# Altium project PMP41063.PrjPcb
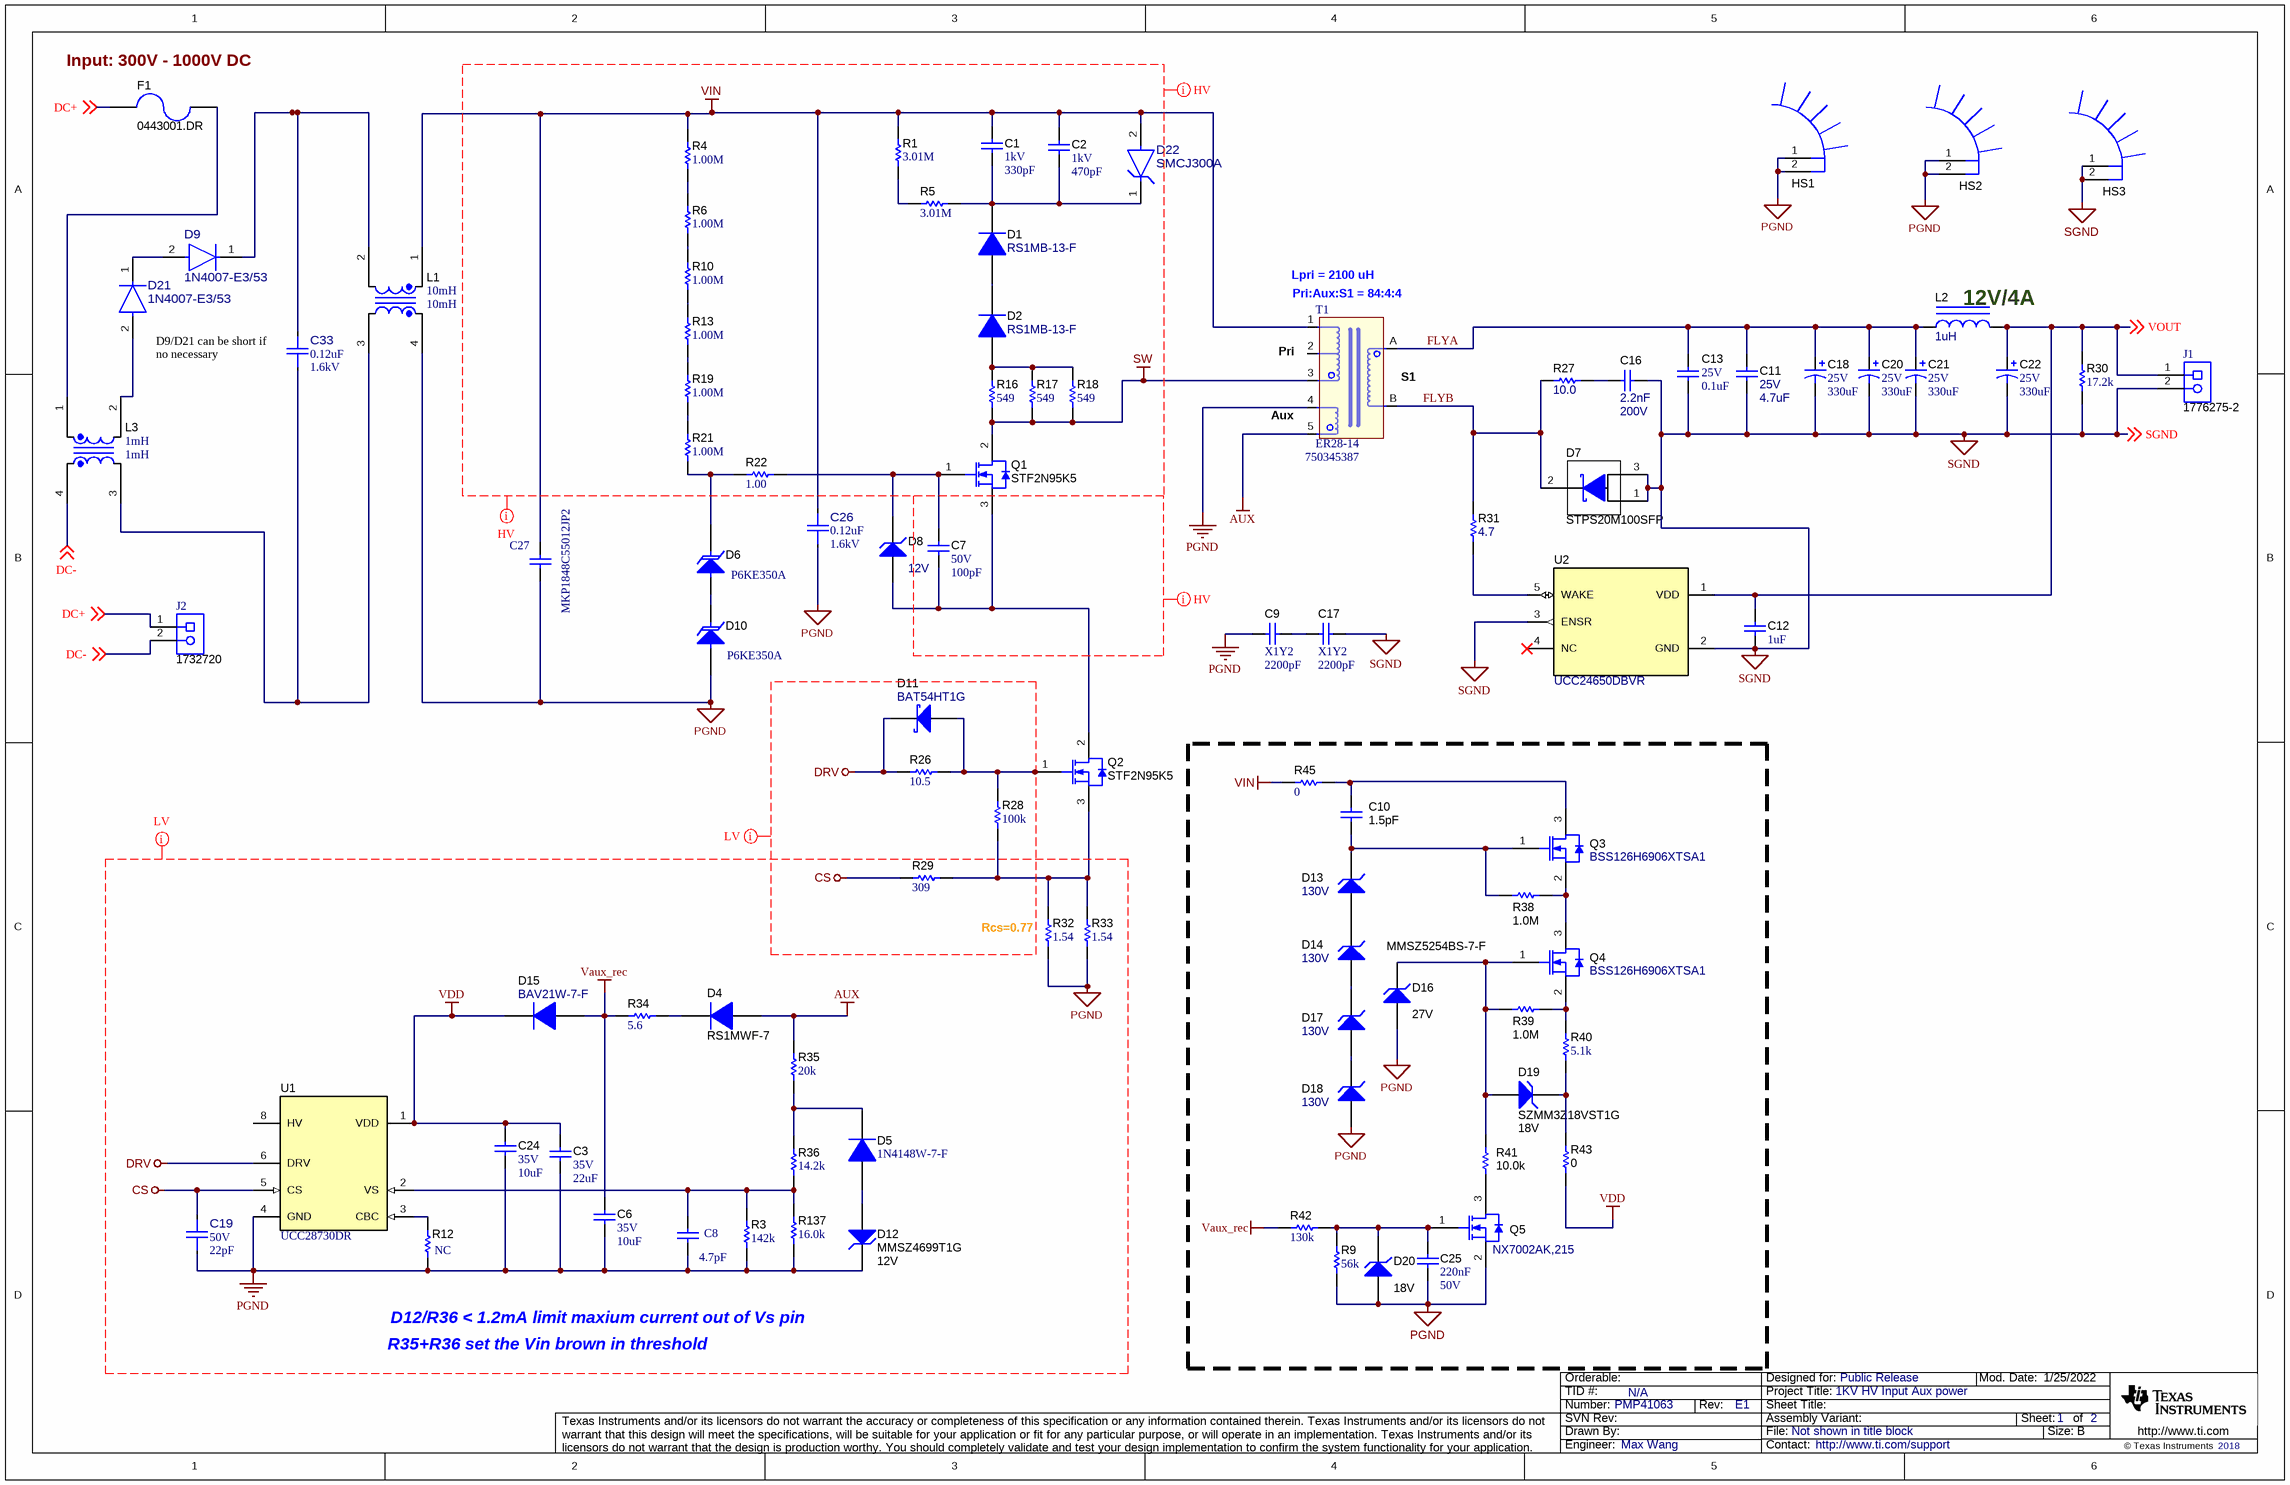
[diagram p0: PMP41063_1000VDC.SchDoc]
CopyrightYear: 2018; PCB_Layout: Max Wang; PCB_Rev: E1; PRJ_Customer: Public Release; PRJ_Engineer: Max Wang; PRJ_Number: PMP41063; PRJ_Title: 1KV HV Input Aux power; SCH_Rev: E1; TechSupport: http://www.ti.com/support; TID: N/A
2 sheets, 105 parts. Net scope: global (net labels, ports and power ports of the same name join across sheets).
Board file: PMP41063.PcbDoc
Sheets:
  PMP41063_1000VDC.SchDoc
  PMP41063_2_Hardware.SchDoc

## Sheet PMP41063_1000VDC.SchDoc
size 431 x 279 mm; Date: Not shown in title block; ApprovedBy: Not shown in title block; CheckedBy: Not shown in title block; Author: Not shown in title block; CompanyName: Not shown in title block; Engineer: Not shown in title block; Organization: Not shown in title block; Address1: Not shown in title block; Address2: Not shown in title block; Address3: Not shown in title block; Address4: Not shown in title block; DocumentNumber: 2; Revision: Use project parameter SCH_Rev; SheetNumber: 1; SheetTotal: 2; PageSetup: Record=PageOptions¦CenterHorizontal=True¦CenterVertical=True¦PrintScale=1.00¦XCorrection=1.00¦YCorrection=1.00¦PrintKind=0¦BorderSize=5000000¦LeftOffset=0¦BottomOffset=0¦Orientation=2¦PaperLength=1000¦PaperWidth=1000¦Scale=100¦PaperSource=15¦PrintQuality=600¦MediaType=1¦DitherType=10¦PaperKind=Letter¦PrintScaleMode=1

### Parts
C1  VDC_V: 1kV  ValueDisplayed: 330pF  [1206]  (hidden comment: GRM31A7U3A331JW31D)
C2  VDC_V: 1kV  ValueDisplayed: 470pF  [1206]  (hidden comment: VJ1206A471JXGAT5Z)
C3  VDC_V: 35V  ValueDisplayed: 22uF  [1206_180]  (hidden comment: C3216X5R1V226M160AC)
C6  VDC_V: 35V  ValueDisplayed: 10uF  [0805_HV]  (hidden comment: GRM21BR6YA106KE43L)
C7  VDC_V: 50V  ValueDisplayed: 100pF  [0805_HV]  (hidden comment: 885012007057)
C8  value 4.7pF  [WCAP-CSGP_0603_L1.6W0.8H0.8_Reflow]  (hidden comment: 885012006030)
C9  AC_Safety: X1Y2  ValueDisplayed: 2200pF  [VY2_900x500_5]  (hidden comment: VY2222M35Y5UG6TV5)
C10  ValueDisplayed: 1.5pF  [1206]  (hidden comment: 1206Y1K01P50DAR)
C11  VDC_V: 25V  ValueDisplayed: 4.7uF  [1206_180]  (hidden comment: GRM31CR71E475KA88L)
C12  ValueDisplayed: 1uF  [0603]  (hidden comment: CMP-0007040-4)
C13  VDC_V: 25V  ValueDisplayed: 0.1uF  [0805_HV]  (hidden comment: GRM21BR71E104KA01L)
C16  Cap_F: 2.2nF  VDC_V: 200V  [0805_HV]  (hidden comment: C0805C222K2RAC)
C17  AC_Safety: X1Y2  ValueDisplayed: 2200pF  [VY2_900x500_5]  (hidden comment: VY2222M35Y5UG6TV5)
C18  VDC_V: 25V  ValueDisplayed: 330uF  [SM_RADIAL_10BMM]  (hidden comment: EEHZC1E331P)
C19  VDC_V: 50V  ValueDisplayed: 22pF  [FP-GCG1885G1H220JA01D_0603-IPC_C]  (hidden comment: GCG1885G1H220JA01D)
C20  VDC_V: 25V  ValueDisplayed: 330uF  [SM_RADIAL_10BMM]  (hidden comment: EEHZC1E331P)
C21  VDC_V: 25V  ValueDisplayed: 330uF  [SM_RADIAL_10BMM]  (hidden comment: EEHZC1E331P)
C22  VDC_V: 25V  ValueDisplayed: 330uF  [SM_RADIAL_10BMM]  (hidden comment: EEHZC1E331P)
C24  VDC_V: 35V  ValueDisplayed: 10uF  [0805_HV]  (hidden comment: GRM21BR6YA106KE43L)
C25  Cap_F: 220nF  VDC_V: 50V  [0603]  (hidden comment: GCJ188R71H224KA01D)
C26  ValueDisplayed: 0.12uF  VDC_V: 1.6kV  [FP-R75TN312050H3J_RADIAL-MFG]  (hidden comment: R75TN312050H3J)
C27  MKP1848C55012JP2  [WCAP-FTBE_L42W31H43]
C33  ValueDisplayed: 0.12uF  VDC_V: 1.6kV  [FP-R75TN312050H3J_RADIAL-MFG]  (hidden comment: R75TN312050H3J)
D1  RS1MB-13-F  [SMB]
D2  RS1MB-13-F  [SMB]
D4  RS1MWF-7  [SOD-123F]
D5  1N4148W-7-F  [SOD-123]
D6  PartNumber: P6KE350A  [DO-15]  (hidden comment: CMP-0006021-3)
D7  STPS20M100SFP  [TO-220FP]
D8  value 12V  [SOD-123]  (hidden comment: MMSZ4699-HE3-08)
D9  1N4007-E3/53  [FP-1N4007-E3/53_DO-41-MFG]
D10  PartNumber: P6KE350A  [DO-15]  (hidden comment: CMP-0006021-3)
D11  BAT54HT1G  [SOD-323]
D12  MMSZ4699T1G  value 12V  [SOD-123]
D13  value 130V  [SOD-323F]  (hidden comment: UDZLVFHTE-17130)
D14  value 130V  [SOD-323F]  (hidden comment: UDZLVFHTE-17130)
D15  BAV21W-7-F  [SOD-123]
D16  MMSZ5254BS-7-F  value 27V  [SOD-323]
D17  value 130V  [SOD-323F]  (hidden comment: UDZLVFHTE-17130)
D18  value 130V  [SOD-323F]  (hidden comment: UDZLVFHTE-17130)
D19  SZMM3Z18VST1G  value 18V  [SOD-323]
D20  value 18V  [SOD-323]  (hidden comment: SZMM3Z18VST1G)
D21  1N4007-E3/53  [FP-1N4007-E3/53_DO-41-MFG]
D22  SMCJ300A  [FP-SMCJ300A_DO214AB-MFG]
F1  0443001.DR  [FUSE_0443]
HS1  CMP-0004071-1  [Aavid_513102B02500G]  (value not drawn)
HS2  CMP-0004071-1  [Aavid_513102B02500G]  (value not drawn)
HS3  CMP-0004071-1  [Aavid_513102B02500G]  (value not drawn)
J1  1776275-2  [TE_1776275-2]
J2  1732720  [Phoenix_1732720]
L1  value 10mH  [WE-CMB_XS]  (hidden comment: 744821110)
L2  ValueDisplayed: 1uH  [WE-PD_7345]  (hidden comment: 744777001)
L3  value 1mH  [WE-CMB_XS]  (hidden comment: 744821201)
Q1  STF2N95K5  [TO-220_FullPAK_Offset]
Q2  STF2N95K5  [TO-220_FullPAK_Offset]
Q3  BSS126H6906XTSA1  [SOT-23]
Q4  BSS126H6906XTSA1  [SOT-23]
Q5  NX7002AK,215  [SOT-23]
R1  ValueDisplayed: 3.01M  [1206]  (hidden comment: CRCW12063M01FKEA)
R3  ValueDisplayed: 142k  [0603]  (hidden comment: RT0603BRD07142KL)
R4  ValueDisplayed: 1.00M  [1206]  (hidden comment: ERJ-8ENF1004V)
R5  ValueDisplayed: 3.01M  [1206]  (hidden comment: CRCW12063M01FKEA)
R6  ValueDisplayed: 1.00M  [1206]  (hidden comment: ERJ-8ENF1004V)
R9  ValueDisplayed: 56k  [0603]  (hidden comment: CRCW060356K0JNEA)
R10  ValueDisplayed: 1.00M  [1206]  (hidden comment: ERJ-8ENF1004V)
R12  Parameter 1: NC  [0603]  (hidden comment: RC0603FR-0751K1L)
R13  ValueDisplayed: 1.00M  [1206]  (hidden comment: ERJ-8ENF1004V)
R16  ValueDisplayed: 549  [1210]  (hidden comment: RC1210FR-07549RL)
R17  ValueDisplayed: 549  [1210]  (hidden comment: RC1210FR-07549RL)
R18  ValueDisplayed: 549  [1210]  (hidden comment: RC1210FR-07549RL)
R19  ValueDisplayed: 1.00M  [1206]  (hidden comment: ERJ-8ENF1004V)
R21  ValueDisplayed: 1.00M  [1206]  (hidden comment: ERJ-8ENF1004V)
R22  ValueDisplayed: 1.00  [1206]  (hidden comment: RC1206FR-071RL)
R26  ValueDisplayed: 10.5  [0805_HV]  (hidden comment: CRCW080510R5FKEA)
R27  ValueDisplayed: 10.0  [0805_HV]  (hidden comment: RC0805FR-0710RL)
R28  ValueDisplayed: 100k  [0603]  (hidden comment: RC0603FR-07100KL)
R29  ValueDisplayed: 309  [0603]  (hidden comment: CRCW0603309RFKEA)
R30  ValueDisplayed: 17.2k  [0805_HV]  (hidden comment: RT0805BRD0717K2L)
R31  ValueDisplayed: 4.7  [0603]  (hidden comment: CRCW06034R70JNEA)
R32  ValueDisplayed: 1.54  [0805_HV]  (hidden comment: CRCW08051R54FKEA)
R33  ValueDisplayed: 1.54  [0805_HV]  (hidden comment: CRCW08051R54FKEA)
R34  ValueDisplayed: 5.6  [0805_HV]  (hidden comment: RC0805JR-075R6L)
R35  ValueDisplayed: 20k  [0603]  (hidden comment: RC0603JR-0720KL)
R36  ValueDisplayed: 14.2k  [0603]  (hidden comment: RT0603BRD0714K2L)
R38  ValueDisplayed: 1.0M  [0603]  (hidden comment: CRCW06031M00JNEA)
R39  ValueDisplayed: 1.0M  [0603]  (hidden comment: CRCW06031M00JNEA)
R40  ValueDisplayed: 5.1k  [0603]  (hidden comment: RC0603JR-075K1L)
R41  ValueDisplayed: 10.0k  [0603]  (hidden comment: CRCW060310K0FKEA)
R42  ValueDisplayed: 130k  [0603]  (hidden comment: RT0603BRD07130KL)
R43  ValueDisplayed: 0  [1206]  (hidden comment: CRCW12060000Z0EA)
R45  ValueDisplayed: 0  [0603]  (hidden comment: CRCW06030000Z0EA)
R137  ValueDisplayed: 16.0k  [0603]  (hidden comment: RC0603FR-0716KL)
T1  ER28-14  PartNumber: 750345387  [ER28-14]
U1  UCC28730DR  [D0007A_N]
U2  UCC24650DBVR  [DBV0005A_N]

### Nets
AUX: D4.2(A) R35.2 T1.5
CS: C19.2 R29.1 U1.5(CS)
DRV: D11.1(K) R26.1 U1.6(DRV)
PGND: C3.2 C6.2 C8.1 C9.1 C19.1 C24.2 C25.2 C26.1 C27.1 D10.2(A) D12.1(K) D16.2(A) D18.2(A) D20.2(A) HS1.1 HS1.2 HS2.1 HS2.2 L1.4 Q5.2(S) R3.1 R9.1 R12.1 R32.1 R33.1 R137.1 T1.4 U1.4(GND)
SGND: C11.2 C12.2 C13.2 C16.1 C17.2 C18.2(-) C20.2(-) C21.2(-) C22.2(-) D7.1(A) D7.3(A) HS3.1 HS3.2 J1.2 R30.1 U2.2(GND) U2.3(ENSR) ; off-sheet SGND
SW: Q1.2(D) R16.1 R17.1 R18.1 T1.3
Vaux_rec: C6.1 D15.2(A) R34.1 R42.1
VDD: C3.1 C24.1 D15.1(K) R43.2 U1.1(VDD)
VIN: C1.1 C2.1 C26.2 C27.2 D22.2(ANODE) L1.1 R1.2 R4.2 R45.1 T1.1
DC+: F1.2 J2.1 ; off-sheet DC+
DC-: J2.2 L3.4 ; off-sheet DC-
FLYA: C11.1 C13.1 C18.1(+) C20.1(+) C21.1(+) L2.1 T1.A
FLYB: D7.2(K) R27.1 R31.2 T1.B
VOUT: C12.1 C22.1(+) J1.1 L2.2 R30.2 U2.1(VDD) ; off-sheet VOUT
NetC1_2: C1.2 C2.2 D1.1(K) D22.1(CATHODE) R5.1
NetC7_1: C7.1 D8.1(K) Q1.1(G) R22.2
NetC7_2: C7.2 D8.2(A) Q1.3(S) Q2.2(D)
NetC8_2: C8.2 R3.2 R36.1 R137.2 U1.2(VS)
NetC9_2: C9.2 C17.1
NetC10_1: C10.1 Q3.3(D) R45.2
NetC10_2: C10.2 D13.1(K) Q3.1(G) R38.1
NetC16_2: C16.2 R27.2
NetC25_1: C25.1 D20.1(K) Q5.1(G) R9.2 R42.2
NetC33_1: C33.1 L1.3 L3.3
NetC33_2: C33.2 D9.1(CATHODE) L1.2
NetD1_2: D1.2(A) D2.1(K)
NetD2_2: D2.2(A) R16.2 R17.2 R18.2
NetD4_1: D4.1(K) R34.2
NetD5_1: D5.1(K) R35.1 R36.2
NetD5_2: D5.2(A) D12.2(A)
NetD6_1: D6.1(K) R21.1 R22.1
NetD6_2: D6.2(A) D10.1(K)
NetD9_2: D9.2(ANODE) D21.1(CATHODE)
NetD11_2: D11.2(A) Q2.1(G) R26.2 R28.1
NetD13_2: D13.2(A) D14.1(K)
NetD14_2: D14.2(A) D17.1(K)
NetD16_1: D16.1(K) D19.2(A) Q4.1(G) R39.1 R41.1
NetD17_2: D17.2(A) D18.1(K)
NetD19_1: D19.1(K) R40.1 R43.1
NetD21_2: D21.2(ANODE) L3.2
NetF1_1: F1.1 L3.1
NetQ2_3: Q2.3(S) R28.2 R29.2 R32.2 R33.2
NetQ3_2: Q3.2(S) Q4.3(D) R38.2
NetQ4_2: Q4.2(S) R39.2 R40.2
NetQ5_3: Q5.3(D) R41.2
NetR1_1: R1.1 R5.2
NetR4_1: R4.1 R6.2
NetR6_1: R6.1 R10.2
NetR10_1: R10.1 R13.2
NetR12_2: R12.2 U1.3(CBC)
NetR13_1: R13.1 R19.2
NetR19_1: R19.1 R21.2
NetR31_1: R31.1 U2.5(WAKE)

Not connected (* = marked no-connect by the designer): T1 2; U1 8(HV); U2 4(NC)*

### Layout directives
net class LV: AUX, CS, DRV, PGND, Vaux_rec, VDD
net class HV: (no net found under the mark), SW, VIN

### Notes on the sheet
- (near F1) Input: 300V - 1000V DC
- (near T1) Lpri = 2100 uH
- (near T1) Pri:Aux:S1 = 84:4:4
- D9/D21 can be short if no necessary
- (near T1) Pri
- 12V/4A
- (near T1) Aux
- (near T1) S1
- (near R32) Rcs=0.77
- R35+R36 set the Vin brown in threshold
- D12/R36 < 1.2mA limit maxium current out of Vs pin

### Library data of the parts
C1 = CMP-0008900-1: CAP, CERM, 330 pF, 1000 V, +/- 5%, U2J, 1206; Manufacturer: MuRata; TaMin_C: -55°C; Polarized: N; SizeAreaWB_mm2: 10.92; Value1: Unknown; U/M: EA; Value: 330pF; TaMax_C: 125°C; SizeZ_mm: 1.35; SizeX_mm: 3.2; SizeY_mm: 1.6; Value2: 1000V; SizeArea_mm2: 5.12; AEC Category: Q200
C2 = CMP-0009035-1: CAP, CERM, 470 pF, 1000 V, +/- 5%, C0G/NP0, 1206; Manufacturer: Vishay-Vitramon; TaMin_C: -55°C; Polarized: N; SizeAreaWB_mm2: 10.92; Value1: Unknown; U/M: EA; Value: 470pF; TaMax_C: 125°C; SizeZ_mm: 1.35; SizeX_mm: 3.2; SizeY_mm: 1.6; Value2: 1000V; SizeArea_mm2: 5.12; AEC Category: Q200
C3 = CMP-0008667-2: CAP, CERM, 22 uF, 35 V, +/- 20%, X5R, 1206; Manufacturer: TDK; TaMin_C: -55°C; ESR_ohm: 2.398m; Polarized: N; SizeAreaWB_mm2: 10.92; Value1: 0.002398 ohm; U/M: EA; Value: 22uF; TaMax_C: 85°C; SizeZ_mm: 1.8; SizeX_mm: 3.2; SizeY_mm: 1.6; SizeArea_mm2: 5.12; Cap_F: 22µF; IRMS_A: 4.6851A; AEC Category: Q200
C6 C24 = CMP-0008310-2: CAP, CERM, 10 uF, 35 V, +/- 10%, X5R, 0805; Manufacturer: MuRata; TaMin_C: -55°C; Polarized: N; SizeAreaWB_mm2: 6.75; Value1: Unknown; U/M: EA; Value: 10uF; TaMax_C: 85°C; SizeZ_mm: 1.45; SizeX_mm: 2; SizeY_mm: 1.25; Cap_Case: 0805; SizeArea_mm2: 2.5; Cap_F: 10µF; AEC Category: Q200
C7 = CMP-0081453-1: CAP, CERM, 100 pF, 50 V,+/- 5%, C0G/NP0, 0805; Manufacturer: Wurth Elektronik; TaMin_C: -55°C; Polarized: N; SizeAreaWB_mm2: 6.75; U/M: EA; Value: 100pF; TaMax_C: 125°C; SizeZ_mm: 1.45; SizeX_mm: 2; SizeY_mm: 1.25; Cap_Case: 0805; SizeArea_mm2: 2.5; AEC Category: Q200
C8 = CMP-0107774-1: WCAP-CSGP Multilayer Ceramic Chip Capacitor, General Purpose, size 0603, NP0, 4.7pF, 25VDC; Manufacturer: Wurth Elektronik; PartNumber: C885012006030; Capacitance Tolerance: +/-0.5pF; Case/Size Code: 0603; Insulation Resistance: 10GOhm; Q Factor: 494; Rated Voltage (DC): 25V; Technical Reference: NP006034R7D025DFCT10000
C9 C17 = CMP-0080613-1: CAP, CERM, 2200 pF, X1 440 VAC/Y2 300 VAC, +/- 20%, Y5U, Body9x5mm; Manufacturer: Vishay-Bccomponents; TaMin_C: -40°C; Polarized: N; SizeAreaWB_mm2: 77; U/M: EA; Value: 2200pF; TaMax_C: 125°C; VAC_Y: 300V; VAC_X: 440V; SizeZ_mm: 13; SizeX_mm: 9; SizeY_mm: 5; Cap_Case: 9x5mm; SizeArea_mm2: 45; Cap_F: 2.2nF; AEC Category: Q200
C10 = CMP-0008597-2: CAP, CERM, 1.5 pF, 1000 V, COG/NPO, 1206; Manufacturer: Knowles Syfer; TaMin_C: -55°C; ESR_ohm: 0.665; Polarized: N; TempCo: C0G/NP0; SizeAreaWB_mm2: 10.92; Value1: 0.665 ohm; U/M: EA; Value: 1.5pF; TaMax_C: 125°C; Tolerance_%: 0.5pF; SizeZ_mm: 1.35; SizeX_mm: 3.2; SizeY_mm: 1.6; Value2: 1000V; SizeArea_mm2: 5.12; AEC Qualified: Y; AEC Category: Q200
C11 = CMP-0008967-2: CAP, CERM, 4.7 uF, 25 V, +/- 10%, X7R, 1206; Manufacturer: MuRata; TaMin_C: -55°C; Polarized: N; SizeAreaWB_mm2: 10.92; Value1: Unknown; U/M: EA; Value: 4.7uF; TaMax_C: 125°C; SizeZ_mm: 1.8; SizeX_mm: 3.2; SizeY_mm: 1.6; Cap_Case: 1206; SizeArea_mm2: 5.12; Cap_F: 4.7µF; AEC Category: Q200
C12 = CMP-0007040-4: CAP, CERM, 1 uF, 25 V, +/- 10%, X7R, 0603; PartNumber: C1608X7R1E105K080AB; Manufacturer: TDK; Polarized: N; Value: 1uF; U/M: EA; Cap_F: 1µF; Value1: Unknown; VDC_V: 25V; TaMin_C: -55°C; TaMax_C: 125°C; SizeAreaWB_mm2: 4.68; SizeZ_mm: 1; SizeX_mm: 1.6; SizeY_mm: 0.8; SizeArea_mm2: 1.28; AEC Category: Q200
C13 = CMP-0008335-2: CAP, CERM, 0.1 uF, 25 V, +/- 10%, X7R, 0805; Manufacturer: MuRata; TaMin_C: -55°C; Polarized: N; SizeAreaWB_mm2: 6.75; Value1: Unknown; U/M: EA; Value: 0.1uF; TaMax_C: 125°C; SizeZ_mm: 1.45; SizeX_mm: 2; SizeY_mm: 1.25; Cap_Case: 0805; SizeArea_mm2: 2.5; Cap_F: 100nF; AEC Category: Q200
C16 = CMP-0007765-2: CAP, CERM, 2200 pF, 200 V, +/- 10%, X7R, 0805; Manufacturer: Kemet; TaMin_C: -55°C; Polarized: N; SizeAreaWB_mm2: 6.75; Value1: Unknown; U/M: EA; Value: 2200pF; TaMax_C: 125°C; SizeZ_mm: 1.45; SizeX_mm: 2; SizeY_mm: 1.25; Cap_Case: 0805; SizeArea_mm2: 2.5; AEC Category: Q200
C18 C20-C22 = CMP-0012593-3: CAP, Polymer Hybrid, 330 uF, 25 V, +/- 20%, 20 ohm, 10x10 SMD; Manufacturer: Panasonic; TaMin_C: -55°C; ESR_ohm: 20; Polarized: Y; SizeAreaWB_mm2: 159.9; Value1: 20 ohm; Value: 330uF; TaMax_C: 125°C; SizeZ_mm: 10.2; SizeX_mm: 11; SizeY_mm: 10.3; SizeArea_mm2: 113.3; CompType: Capacitor; Cap_F: 330µF; IRMS_A: 2A; AEC Category: Q200
C19 = CMP-0095693-1: AgPd Termination Conductive Glue Mounting Chip Multilayer Ceramic Capacitors for Automotive 22pF with 5% as tolerance, 50V X8G 30ppm/°C, 0603 Package; Manufacturer: Murata; Tolerance_%: 0.05%; AEC Qualified: Yes; SizeZ_mm: 0.9mm; AEC Grade: Grade 0
C25 = CMP-0079579-1: CAP, CERM, 0.22 µF, 50 V,+/- 10%, X7R, AEC-Q200 Grade 1, 0603; Manufacturer: MuRata; SizeAreaWB_mm2: 4.68; SizeArea_mm2: 1.28; AEC Qualified: Y; AEC Category: Q200; Value: 0.22uF; TaMax_C: 125°C; SizeZ_mm: 1; Polarized: N; TaMin_C: -55°C; SizeY_mm: 0.8; U/M: EA; SizeX_mm: 1.6; ValueDisplayed: 0.22µF
C26 C33 = CMP-0095721-1: 0.12 µF Film Capacitor 650V 1600V (1.6kV) Polypropylene (PP), Metallized Radial; Manufacturer: KEMET; Tolerance_%: 5%; AEC Qualified: Yes; AEC Grade: Grade 1; Value: 120nF; SizeZ_mm: 22.1mm
C27 = 890493428013CS: Film Capacitor THT 5µF, 1200V; Manufacturer: VISHAY; Match Code: WCAP-FTBE; Capacitance Tolerance: +/-10%; Dissipation Factor @1kHz: 1%; Dissipation Factor @10kHz: 2%; Dissipation Factor @100kHz: 10%; Insulation Resistance: 3000Ω x F; Pitch: 37.5mm; Rate of Voltage Rise: 16V/µs; Technical Reference: MPSP375475KA00DCPP25004; Value: 5uF
D1 D2 = CMP-0076889-1: Diode, P-N, 1000 V, 1 A, SMB; Manufacturer: Diodes Inc.; SizeAreaWB_mm2: 44.156; Vr_V: 1kV; SizeArea_mm2: 21.336; TJmax_C: 150°C; AEC Category: Q101; Value: 1000V; SizeZ_mm: 2.6; Green_REACh: Passed; Io_A: 1A; Vf_V: 1.3V; SizeY_mm: 3.81; Green_Lifecycle: Active; U/M: EA; SizeX_mm: 5.6; RJC_CperW: 20.0
D4 = CMP-0082234-2: Diode, Fast Rectifier, 1000 V, 1 A, SOD-123F; Manufacturer: Diodes Inc.; SizeX_mm: 3.5; Vf_V: 1.3V; SizeZ_mm: 1.1; TJmax_C: 150°C; SizeY_mm: 1.6; AEC Category: Q101; Io_A: 1A; Value: 1000V; AEC Qualified: N; SizeArea_mm2: 5.6; Vr_V: 1kV; RJC_CperW: 10; SizeAreaWB_mm2: 11.7
D5 = CMP-0029001-1: Diode, Ultrafast, 100 V, 0.15 A, SOD-123; Manufacturer: Diodes Inc.; Io_A: 150mA; Green_Lifecycle: Active; SizeAreaWB_mm2: 13.095; Vr_V: 100V; Green_REACh: Passed; Value1: 0.15A; TJmax_C: 150°C; U/M: EA; Value: 100V; SizeZ_mm: 1.35; SizeX_mm: 3.85; SizeY_mm: 1.7; Vf_V: 1.25V; SizeArea_mm2: 6.545; AEC Category: Q101
D6 D10 = CMP-0006021-3: Diode, TVS, Uni, 300 V, 482 Vc, DO-15; Manufacturer: Fairchild Semiconductor; Value: 300V; Value1: 600W; AEC Category: Q101; Ipp: 1.3A; Vc: 482V; Vbr_Min: 332V; Vbr_Max: 368V
D7 = CMP-0028887-2: Diode, Schottky, 100 V, 20 A, TH; Manufacturer: STMicroelectronics; Io_A: 20A; Green_Lifecycle: Not Set; SizeAreaWB_mm2: 79.3; Vr_V: 100V; Green_REACh: Incomplete; TJmax_C: 150°C; U/M: EA; Value: 100V; SizeZ_mm: 20; SizeX_mm: 10.2; SizeY_mm: 4.5; Vf_V: 8.5dV; Value2: 0.85V; SizeArea_mm2: 45.9; AEC Qualified: N; AEC Category: Q101; RJC_CperW: 4
D8 = CMP-0077572-3: Diode, Zener, 12 V, 500 mW, AEC-Q101, SOD-123; Manufacturer: Vishay-Semiconductor; SizeX_mm: 3.85; AEC Category: Q101; AEC Qualified: Y; SizeZ_mm: 1.35; SizeArea_mm2: 6.545; RJA_CperW: 340; SizeY_mm: 1.7; SizeAreaWB_mm2: 13.095; Value1: 0.5W; Power_W: 500mW
D9 D21 = CMP-0096268-1: Diode Standard 1000 V 1A Through Hole DO-204AL (DO-41); Manufacturer: Vishay; TJmax_C: 150°C; Vf_V: 1kV; SizeZ_mm: 2.7mm; AEC Qualified: No; Peak Reverse Current: 5uA; Max Surge Forward Current: 30A; ValueDisplayed: 15pF
D11 = CMP-0028455-2: Diode, Schottky, 30 V, 0.2 A, SOD-323; Manufacturer: ON Semiconductor; Vr_V: 30V; Value: 30V; SizeZ_mm: 1; Value1: 0.2A; SizeAreaWB_mm2: 8.695; Vf_V: 350mV; Io_A: 200mA; SizeX_mm: 2.7; SizeY_mm: 1.35; Green_Lifecycle: Active; AEC Category: Q101; Value2: 0.35V; SizeArea_mm2: 3.645; Green_REACh: Passed
D12 = CMP-0005742-3: Diode, Zener, 12 V, 500 mW, SOD-123; Manufacturer: ON Semiconductor; SizeArea_mm2: 6.545; RJA_CperW: 340; SizeZ_mm: 1.35; SizeY_mm: 1.7; Value1: 0.5W; SizeX_mm: 3.85; Power_W: 500mW; AEC Category: Q101; SizeAreaWB_mm2: 13.095
D13 D14 D17 D18 = CMP-0082118-3: Diode, Zener, 130 V, 200 mW, SOD-323F, AEC-Q101; Manufacturer: Rohm; SizeZ_mm: 0.8; AEC Category: Q101; Power_W: 200mW; SizeY_mm: 1.25; SizeAreaWB_mm2: 7.875; Value1: 0.2W; SizeArea_mm2: 3.125; SizeX_mm: 2.5; AEC Qualified: Yes
D15 = CMP-0029031-2: Diode, Switching, 200 V, 0.2 A, SOD-123; Manufacturer: Diodes Inc.; Green_REACh: Passed; SizeArea_mm2: 6.545; TJmax_C: 150°C; Value2: 1.25V; Io_A: 200mA; SizeAreaWB_mm2: 13.095; SizeY_mm: 1.7; Value: 200V; Green_Lifecycle: Active; SizeX_mm: 3.85; SizeZ_mm: 1.35; AEC Category: Q101; Value1: 0.2A
D16 = CMP-0005839-3: Diode, Zener, 27 V, 200 mW, SOD-323; Manufacturer: Diodes Inc.; AEC Category: Q101; Power_W: 200mW; Value1: 0.2W; SizeZ_mm: 1; SizeArea_mm2: 3.645; SizeX_mm: 2.7; SizeY_mm: 1.35; RJA_CperW: 350; SizeAreaWB_mm2: 8.695
D19 D20 = CMP-0085765-1: Diode, Zener, 18 V, 300 mW, AEC-Q101, SOD-323; Manufacturer: ON Semiconductor; Value1: 0.3W; SizeX_mm: 2.7; RJA_CperW: 416; SizeArea_mm2: 3.645; AEC Category: Q101; SizeZ_mm: 1; Power_W: 300mW; AEC Qualified: Y; SizeY_mm: 1.35; SizeAreaWB_mm2: 8.695
D22 = CMP-0088475-2: 486V Clamp 3.1A Ipp Tvs Diode Surface Mount DO-214AB (SMCJ); Manufacturer: Littelfuse Inc; TJmax_C: +150°C; VRWM: 300V; Direction: Unidirectional; Breakdown Voltage: 335V; Number Of Channels: 1; AEC Qualified: No; SizeZ_mm: 2.62mm; AEC Category: Q101; Ppk: 1.5kW
F1 = CMP-0003467-2: Fuse, 1 A, 250VAC/VDC, SMD; Manufacturer: Littelfuse; Irating_A: 1A; Interrupt_AC: 50A; Interrupt_DC: 250A; VAC_V: 250V; Rtyp_Ohm: 0.18; MeltingTyp: 10.17
HS1-HS3 = CMP-0004071-1: Extruded heat sink with radial fins; Manufacturer: Aavid; PartNumber: 513102B02500G
J1 = CMP-0054987-1: Terminal Block, 3.5mm, 2x1, Tin, TH; Manufacturer: TE Connectivity; CNHeader: FALSE; Current_A: 7A; Green_Lifecycle: Active; Gender: Female; Green_REACh: Passed; Voltage_V: 250V; Row_Count: 1; Pitch_mm: 3.5; CT: TRUE; Cert_UL: Y
J2 = CMP-0055482-1: Terminal Block, 2x1, 7.62mm, TH; Manufacturer: Phoenix Contact; CT: TRUE; CNHeader: FALSE
L1 = CMP-0076840-1: Coupled inductor, 10 mH, 0.7 A, 0.35 ohm, TH; Manufacturer: Wurth Elektronik; SizeAreaWB_mm2: 161.5; SizeArea_mm2: 112.5; AEC Category: Q200; SizeZ_mm: 20.5; SizeY_mm: 7.5; DCR_ohm: 0.35; SizeX_mm: 15.0
L2 = CMP-0064262-1: Inductor, Shielded Drum Core, Metal Composite, 1 uH, 8 A, 0.0084 ohm, SMD; Manufacturer: Wurth Elektronik; Isat: 9A @ 10% inductance drop; Irms: 8A @ 40C rise; Green_Lifecycle: Active; SizeAreaWB_mm2: 86.49; DCR_ohm: 8.4m; Green_REACh: Passed; Value: 1uH; Imax_A: 8A; SizeZ_mm: 4.5; SizeX_mm: 7.3; SizeArea_mm2: 53.29; Ind_H: 1µH; AEC Category: Q200
L3 = CMP-0013113-2: Coupled inductor, 1 mH, 2 A, 0.045 ohm, TH; Manufacturer: Wurth Elektronik; SizeAreaWB_mm2: 161.5; DCR_ohm: 45m; SizeZ_mm: 20.5; SizeX_mm: 15; SizeY_mm: 7.5; SizeArea_mm2: 112.5
Q1 = CMP-0001279-3: MOSFET N-CH 950V 2A TO220FP; PartNumber: STF10N80K5; Alternate Manufacturer: None; Manufacturer: STMicroelectronics; RevisionId: 1; AccessRights: 2147483647; Folder: Unified Components\Transistors\MOSFET\N-Channel\VDS 200 V+\; ContentType: Component; SizeZ_mm: 20; ChType: N; Value2: 22 nC; VdsMax_V: 800V; SizeX_mm: 10.2; SizeY_mm: 4.5; Vgs_V: 30V; QgTyp_nC: 22; SizeArea_mm2: 45.9; AEC Category: Q101; IdsMax_A: 9A; SizeAreaWB_mm2: 79.3; U/M: EA
Q2 = CMP-0001279-3: MOSFET, N-CH, 800 V, 9 A, TO-220FP; PartNumber: STF10N80K5; Alternate Manufacturer: None; Manufacturer: STMicroelectronics; RevisionId: 1; AccessRights: 2147483647; Folder: Unified Components\Transistors\MOSFET\N-Channel\VDS 200 V+\; ContentType: Component; SizeZ_mm: 20; ChType: N; Value2: 22 nC; VdsMax_V: 800V; SizeX_mm: 10.2; SizeY_mm: 4.5; Vgs_V: 30V; QgTyp_nC: 22; Value: 800V; SizeArea_mm2: 45.9; AEC Category: Q101; IdsMax_A: 9A; SizeAreaWB_mm2: 79.3; U/M: EA
Q3 Q4 = CMP-0001147-4: MOSFET, N-CH, Depletion Mode, 600 V, 0.021 A, SOT-23, AEC-Q101; Manufacturer: Infineon Technologies; SizeZ_mm: 1.1; ChType: N; Value2: 1.4 nC; VdsMax_V: 600V; SizeX_mm: 2.5; SizeY_mm: 3; Vgs_V: 20V; QgTyp_nC: 1.4; Value: 600V; SizeArea_mm2: 7.5; IdsMax_A: 21mA; SizeAreaWB_mm2: 14; U/M: EA
Q5 = CMP-0000769-1: MOSFET, N-CH, 60 V, 0.19 A, SOT-23; Manufacturer: Nexperia USA Inc; SizeZ_mm: 1.1; ChType: N; VdsMax_V: 60V; SizeX_mm: 2.5; SizeY_mm: 3; Vgs_V: 20V; Value: 60V; Rdson45_ohm: 7.5; IdsMax_A: 190mA; SizeAreaWB_mm2: 14; U/M: EA; QgTyp_nC: 223
R1 R5 = CMP-0016956-3: RES, 3.01 M, 1%, 0.25 W, AEC-Q200 Grade 0, 1206; Manufacturer: Vishay-Dale; Power_W: 250mW; TempCo: 100 ppm/C; Value_Code: 3M01; Value: 3.01Meg; EIA_Code: E96; SizeX_mm: 3.2; SizeY_mm: 1.6; SizeZ_mm: 1.35; Value2: 0.25W; SizeArea_mm2: 5.12; AEC Qualified: Y; VDC_V: 200V; AEC Category: Q200; AEC Grade: 0
R3 = CMP-0023744-1: RES, 142 k, 0.1%, 0.1 W, 0603; Manufacturer: Yageo America; Power_W: 100mW; TempCo: 25 ppm/C; U/M: EA; Value: 142k; EIA_Code: E192; SizeX_mm: 1.6; SizeY_mm: 0.8; SizeZ_mm: 1; Value2: 0.1W; SizeArea_mm2: 1.28; VDC_V: 75V; AEC Category: Q200
R4 R6 R10 R13 R19 R21 = CMP-0017286-3: RES, 1.00 M, 1%, 0.25 W, AEC-Q200 Grade 0, 1206; Manufacturer: Panasonic; Power_W: 250mW; TempCo: 100 ppm/C; Value_Code: 1M00; Value: 1.00Meg; EIA_Code: E96; Res_ohm: 1M; SizeX_mm: 3.2; SizeY_mm: 1.6; SizeZ_mm: 1.35; Value2: 0.25W; SizeArea_mm2: 5.12; AEC Qualified: Y; VDC_V: 200V; AEC Category: Q200; AEC Grade: 0; SizeAreaWB_mm2: 10.92
R9 = CMP-0025828-4: RES, 56 k, 5%, 0.1 W, AEC-Q200 Grade 0, 0603; Manufacturer: Vishay-Dale; Power_W: 100mW; TempCo: 200 ppm/C; Value_Code: 56k0; Value: 56k; EIA_Code: E24; SizeX_mm: 1.6; SizeY_mm: 0.8; SizeZ_mm: 1; Value2: 0.1W; SizeArea_mm2: 1.28; AEC Qualified: Y; VDC_V: 75V; AEC Category: Q200; AEC Grade: 0
R12 = CMP-0023166-5: RES, 51.1 k, 1%, 0.1 W, 0603; Manufacturer: Yageo; Power_W: 100mW; TempCo: 100 ppm/C; Value_Code: 51k1; Value: 51.1k; EIA_Code: E96; SizeX_mm: 1.6; SizeY_mm: 0.8; SizeZ_mm: 1; Value2: 0.1W; SizeArea_mm2: 1.28; AEC Qualified: N; VDC_V: 75V; AEC Category: Q200; SizeAreaWB_mm2: 4.68
R16-R18 = CMP-0083252-1: RES, 549, 1%, 0.5 W, 1210; Manufacturer: Yageo; Power_W: 500mW; TempCo: 100 ppm/C; SizeAreaWB_mm2: 14.7; Value_Code: 549R; Value: 549; EIA_Code: E96; SizeX_mm: 3.2; SizeY_mm: 2.5; SizeZ_mm: 1.35; Value2: 0.5W; SizeArea_mm2: 8; AEC Qualified: N; VDC_V: 200V; AEC Category: Q200
R22 = CMP-0018059-2: RES, 1.00, 1%, 0.25 W, 1206; Manufacturer: Yageo America; Power_W: 250mW; TempCo: 200 ppm/C; Value_Code: 1R00; U/M: EA; Value: 1.00; EIA_Code: E96; Res_ohm: 1; SizeX_mm: 3.2; SizeY_mm: 1.6; SizeZ_mm: 1.35; Value2: 0.25W; SizeArea_mm2: 5.12; VDC_V: 200V; AEC Category: Q200
R26 = CMP-0020849-3: RES, 10.5, 1%, 0.125 W, AEC-Q200 Grade 0, 0805; Manufacturer: Vishay-Dale; Power_W: 125mW; TempCo: 100 ppm/C; Value_Code: 10R5; Value: 10.5; EIA_Code: E96; SizeX_mm: 2; SizeY_mm: 1.25; SizeZ_mm: 1.45; Value2: 0.125W; SizeArea_mm2: 2.5; AEC Qualified: Y; VDC_V: 150V; AEC Category: Q200; AEC Grade: 0
R27 = CMP-0021863-2: RES, 10.0, 1%, 0.125 W, 0805; Manufacturer: Yageo America; Power_W: 125mW; TempCo: 200 ppm/C; Value_Code: 10R0; U/M: EA; Value: 10.0; EIA_Code: E96; Res_ohm: 10; SizeX_mm: 2; SizeY_mm: 1.25; SizeZ_mm: 1.45; Value2: 0.125W; SizeArea_mm2: 2.5; VDC_V: 150V; AEC Category: Q200
R28 = CMP-0022735-5: RES, 100 k, 1%, 0.1 W, 0603; Manufacturer: Yageo; Power_W: 100mW; TempCo: 100 ppm/C; Value: 100k; EIA_Code: E96; SizeX_mm: 1.6; SizeY_mm: 0.8; SizeZ_mm: 1; Value2: 0.1W; SizeArea_mm2: 1.28; AEC Qualified: N; VDC_V: 75V; AEC Category: Q200; SizeAreaWB_mm2: 4.68
R29 = CMP-0022323-5: RES, 309, 1%, 0.1 W, AEC-Q200 Grade 0, 0603; Manufacturer: Vishay-Dale; Power_W: 100mW; TempCo: 100 ppm/C; Value_Code: 309R; Value: 309; EIA_Code: E96; SizeX_mm: 1.6; SizeY_mm: 0.8; SizeZ_mm: 1; Value2: 0.1W; SizeArea_mm2: 1.28; AEC Qualified: Y; VDC_V: 75V; AEC Category: Q200; AEC Grade: 0
R30 = CMP-0019626-1: RES, 17.2 k, 0.1%, 0.125 W, 0805; Manufacturer: Yageo America; Power_W: 125mW; TempCo: 25 ppm/C; Value_Code: 17k2; U/M: EA; Value: 17.2k; EIA_Code: E192; SizeX_mm: 2; SizeY_mm: 1.25; SizeZ_mm: 1.45; Value2: 0.125W; SizeArea_mm2: 2.5; VDC_V: 150V; AEC Category: Q200
R31 = CMP-0025821-1: RES, 4.7, 5%, 0.1 W, 0603; Manufacturer: Vishay-Dale; Power_W: 100mW; TempCo: 200 ppm/C; Value_Code: 4R70; U/M: EA; Value: 4.7; EIA_Code: E24; SizeX_mm: 1.6; SizeY_mm: 0.8; SizeZ_mm: 1; Value2: 0.1W; SizeArea_mm2: 1.28; VDC_V: 75V; AEC Category: Q200
R32 R33 = CMP-0021027-1: RES, 1.54, 1%, 0.125 W, 0805; Manufacturer: Vishay-Dale; Power_W: 125mW; TempCo: 100 ppm/C; Value_Code: 1R54; U/M: EA; Value: 1.54; EIA_Code: E96; SizeX_mm: 2; SizeY_mm: 1.25; SizeZ_mm: 1.45; Value2: 0.125W; SizeArea_mm2: 2.5; VDC_V: 150V; AEC Category: Q200
R34 = CMP-0020824-1: RES, 5.6, 5%, 0.125 W, 0805; Manufacturer: Yageo America; Power_W: 125mW; TempCo: 200 ppm/C; Value_Code: 5R60; U/M: EA; Value: 5.6; EIA_Code: E24; SizeX_mm: 2; SizeY_mm: 1.25; SizeZ_mm: 1.45; Value2: 0.125W; SizeArea_mm2: 2.5; VDC_V: 150V; AEC Category: Q200
R35 = CMP-0025900-5: RES, 20 k, 5%, 0.1 W, 0603; Manufacturer: Yageo; Power_W: 100mW; TempCo: 100 ppm/C; Value_Code: 20k0; Value: 20k; EIA_Code: E24; SizeX_mm: 1.6; SizeY_mm: 0.8; SizeZ_mm: 1; Value2: 0.1W; SizeArea_mm2: 1.28; AEC Qualified: N; VDC_V: 75V; AEC Category: Q200; SizeAreaWB_mm2: 4.68
R36 = CMP-0023754-1: RES, 14.2 k, 0.1%, 0.1 W, 0603; Manufacturer: Yageo America; Power_W: 100mW; TempCo: 25 ppm/C; Value_Code: 14k2; U/M: EA; Value: 14.2k; EIA_Code: E192; SizeX_mm: 1.6; SizeY_mm: 0.8; SizeZ_mm: 1; Value2: 0.1W; SizeArea_mm2: 1.28; VDC_V: 75V; AEC Category: Q200
R38 R39 = CMP-0025736-4: RES, 1.0 M, 5%, 0.1 W, AEC-Q200 Grade 0, 0603; Manufacturer: Vishay-Dale; Power_W: 100mW; TempCo: 200 ppm/C; Value_Code: 1M00; Value: 1.0Meg; EIA_Code: E24; Res_ohm: 1M; SizeX_mm: 1.6; SizeY_mm: 0.8; SizeZ_mm: 1; Value2: 0.1W; SizeArea_mm2: 1.28; AEC Qualified: Y; VDC_V: 75V; AEC Category: Q200; AEC Grade: 0
R40 = CMP-0025932-5: RES, 5.1 k, 5%, 0.1 W, 0603; Manufacturer: Yageo; Power_W: 100mW; TempCo: 100 ppm/C; Value_Code: 5k10; Value: 5.1k; EIA_Code: E24; SizeX_mm: 1.6; SizeY_mm: 0.8; SizeZ_mm: 1; Value2: 0.1W; SizeArea_mm2: 1.28; AEC Qualified: N; VDC_V: 75V; AEC Category: Q200; SizeAreaWB_mm2: 4.68
R41 = CMP-0021998-4: RES, 10.0 k, 1%, 0.1 W, AEC-Q200 Grade 0, 0603; Manufacturer: Vishay-Dale; Power_W: 100mW; TempCo: 100 ppm/C; Value_Code: 10k0; Value: 10.0k; EIA_Code: E96; Res_ohm: 10k; SizeX_mm: 1.6; SizeY_mm: 0.8; SizeZ_mm: 1; Value2: 0.1W; SizeArea_mm2: 1.28; AEC Qualified: Y; VDC_V: 75V; AEC Category: Q200; AEC Grade: 0
R42 = CMP-0023718-2: RES, 130 k, 0.1%, 0.1 W, 0603; Manufacturer: Yageo America; Power_W: 100mW; TempCo: 25 ppm/C; U/M: EA; Value: 130k; EIA_Code: E192; SizeX_mm: 1.6; SizeY_mm: 0.8; SizeZ_mm: 1; Value2: 0.1W; SizeArea_mm2: 1.28; VDC_V: 75V; AEC Category: Q200
R43 = CMP-0018573-3: RES, 0, 5%, 0.25 W, AEC-Q200 Grade 0, 1206; Manufacturer: Vishay-Dale; Power_W: 250mW; TempCo: 200 ppm/C; Value_Code: 0000; Value: 0; EIA_Code: E24; SizeX_mm: 3.2; SizeY_mm: 1.6; SizeZ_mm: 1.35; Value2: 0.25W; SizeArea_mm2: 5.12; AEC Qualified: Y; VDC_V: 200V; AEC Category: Q200
R45 = CMP-0025697-2: RES, 0, 5%, 0.1 W, 0603; Manufacturer: Vishay-Dale; Power_W: 100mW; TempCo: 200 ppm/C; Value_Code: 0000; U/M: EA; Value: 0; EIA_Code: E24; SizeX_mm: 1.6; SizeY_mm: 0.8; SizeZ_mm: 1; Value2: 0.1W; SizeArea_mm2: 1.28; VDC_V: 75V; AEC Category: Q200
R137 = CMP-0022831-5: RES, 16.0 k, 1%, 0.1 W, 0603; Manufacturer: Yageo; Power_W: 100mW; TempCo: 100 ppm/C; Value_Code: 16k0; Value: 16.0k; Res_ohm: 16k; SizeX_mm: 1.6; SizeY_mm: 0.8; SizeZ_mm: 1; Value2: 0.1W; SizeArea_mm2: 1.28; AEC Qualified: N; VDC_V: 75V; AEC Category: Q200; SizeAreaWB_mm2: 4.68
T1 = ER28-14: Manufacturer: Wurth
U1 = CMP-0074089-2: Zero Standby PSR Flyback Controller with CVCC and Wake-Up Monitoring, D0007A (SOIC-7); Alternate Manufacturer: Texas Instruments; SizeAreaWB_mm2: 55.2; U/M: EA; SizeZ_mm: 1.75; SizeX_mm: 6.0; SizeY_mm: 4.9; SizeArea_mm2: 29.4; CompType: IC; AEC Category: Q200; AEC Qualified: N
U2 = CMP-0067258-1: 200-V Wake-up Monitor for Fast Transient Primary-side Regulation, DBV0005A (SOT-23-5); Alternate PartNumber: UCC24650DBVT; Alternate Manufacturer: Texas Instruments; Green_Lifecycle: Active; SizeAreaWB_mm2: 14.82; Green_REACh: Passed; U/M: EA; SizeZ_mm: 1.45; SizeX_mm: 2.8; SizeY_mm: 2.9; SizeArea_mm2: 8.12; CompType: IC

## Sheet PMP41063_2_Hardware.SchDoc
size 431 x 279 mm; Date: Not shown in title block; ApprovedBy: Not shown in title block; CheckedBy: Not shown in title block; Author: Not shown in title block; CompanyName: Not shown in title block; Engineer: Not shown in title block; Organization: Not shown in title block; Address1: Not shown in title block; Address2: Not shown in title block; Address3: Not shown in title block; Address4: Not shown in title block; DocumentNumber: 3; Revision: Use project parameter SCH_Rev; SheetNumber: 2; SheetTotal: 2; PageSetup: Record=PageOptions¦CenterHorizontal=True¦CenterVertical=True¦PrintScale=1.00¦XCorrection=1.00¦YCorrection=1.00¦PrintKind=0¦BorderSize=5000000¦LeftOffset=0¦BottomOffset=0¦Orientation=2¦PaperLength=1000¦PaperWidth=1000¦Scale=100¦PaperSource=15¦PrintQuality=600¦MediaType=1¦DitherType=10¦PaperKind=Letter¦PrintScaleMode=1
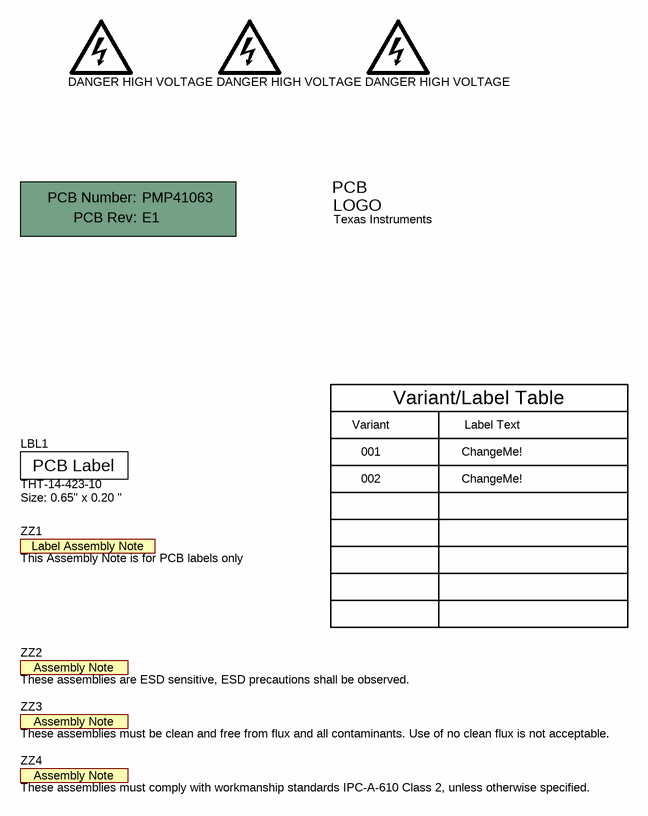
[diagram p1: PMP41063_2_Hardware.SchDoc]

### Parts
LBL1  THT-14-423-10  Note: Size: 0.65" x 0.20 "  [Label_650x200]
LOGO1  DANGER HIGH VOLTAGE  [IEC_HighVoltage_Small]
LOGO2  DANGER HIGH VOLTAGE  [IEC_HighVoltage_Small]
LOGO3  DANGER HIGH VOLTAGE  [IEC_HighVoltage_Small]
Logo5  Texas Instruments  [TI_Stacked_Overlay_Small]  (no BOM)
PCB1  Printed Circuit Board  (value not drawn)  (mechanical)
ZZ1  This Assembly Note is for PCB labels only  [AssemblyNoteLabel]  (no BOM)
ZZ2  These assemblies are ESD sensitive, ESD precautions shall be observed.  [AssemblyNote]  (no BOM)
ZZ3  These assemblies must be clean and free from flux and all contaminants. Use of no clean flux is not acceptable.  [AssemblyNote]  (no BOM)
ZZ4  These assemblies must comply with workmanship standards IPC-A-610 Class 2, unless otherwise specified.  [AssemblyNote]  (no BOM)

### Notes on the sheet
- Variant
- Variant/Label Table
- Label Text
- 001
- 002
- ChangeMe!

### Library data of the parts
LBL1 = CMP-0003625-1: Thermal Transfer Printable Labels, 0.650" W x 0.200" H - 10,000 per roll; Manufacturer: Brady; CompType: Label
LOGO1-LOGO3 = CMP-0074835-1: IEC 61010-1 High Voltage Warning; SymbolCreator: a0412235
Logo5 = CMP-0074838-1: Texas Instrument Corporate Signature; SymbolCreator: a0412235; Lib Reference: TI_Logo; Library Reference: Logo
PCB1 = CMP-0003618-2: Manufacturer: Any; PartNumber: PMP41063
ZZ1 = CMP-0003616-3
ZZ2 = CMP-0077236-1
ZZ3 = CMP-0077237-1
ZZ4 = CMP-0077238-1

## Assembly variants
001: not fitted D9 D21 R12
